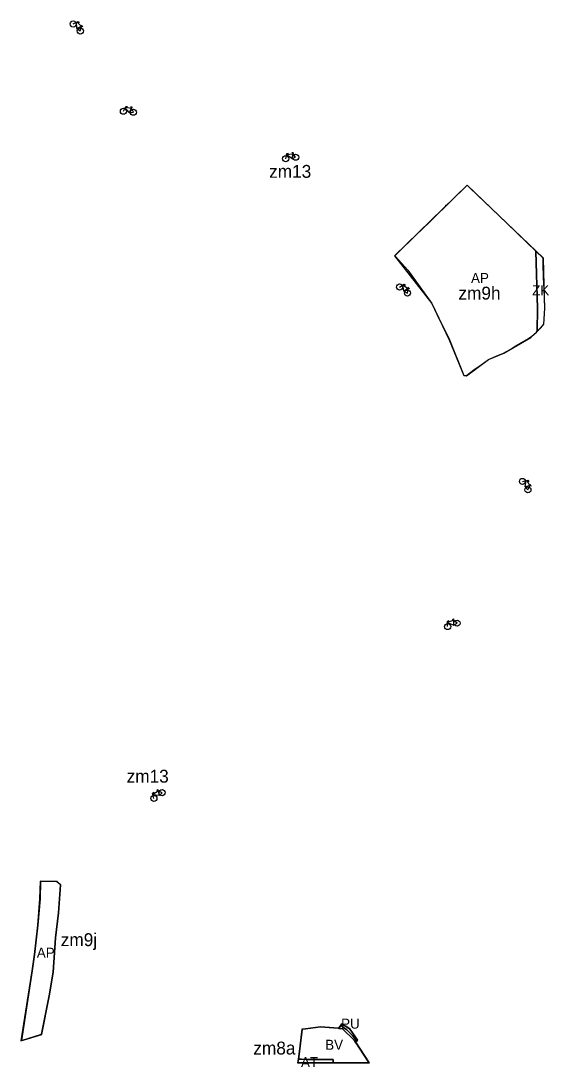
# Model space of a CAD drawing. Extents: x -555070 to -553076, y -1186731 to -1182766.
# Drawn here: x -554996 to -554258, y -1184227 to -1182766 of the extents above; entities that cross this region are included whole.
import ezdxf

# ---------------------------------------------------------------- set-up
doc = ezdxf.new("R2010")
doc.units = 0
for name, color, linetype in [('HRANICE_ZMENY_DO_KOO', 7, 'Continuous'), ('Level 10', 7, 'Continuous'), ('Level 13', 7, 'Continuous'), ('Level 52', 7, 'Continuous'), ('Level 58', 7, 'Continuous'), ('Level 59', 7, 'Continuous'), ('MISTNI_KOMUNIKACE_stav', 7, 'Continuous'), ('OBRYS_PLOCH', 7, 'Continuous'), ('stav_AP', 7, 'Continuous'), ('stav_AT', 7, 'Continuous'), ('stav_BV', 7, 'Continuous'), ('stav_PU', 7, 'Continuous'), ('stav_ZK', 7, 'Continuous'), ('ZU_plocha_aktualizace', 7, 'Continuous')]:
    doc.layers.add(name, color=color, linetype=linetype)

msp = doc.modelspace()

# ---------------------------------------------------------------- linework, layer by layer
at = {"layer": 'HRANICE_ZMENY_DO_KOO'}
for points in [[(-554368.6, -1182998.9), (-554372.7, -1182994.9), (-554473.9, -1183093.6), (-554421.9, -1183160.4), (-554397.6, -1183211.2), (-554377.3, -1183261), (-554373.3, -1183261.3), (-554342.6, -1183238.7), (-554321.4, -1183229.8), (-554283.7, -1183207.7), (-554274.5, -1183199.2), (-554265.2, -1183189.4), (-554263.8, -1183167.5), (-554265, -1183134), (-554266, -1183097)], [(-554940.1, -1183972.4), (-554945.6, -1183967.6), (-554969.2, -1183967.3), (-554969.9, -1183991.9), (-554973.1, -1184028.8), (-554977.7, -1184069.8), (-554980.9, -1184092.6), (-554996.1, -1184190.5), (-554966.8, -1184181.4), (-554956.2, -1184127.4), (-554950.7, -1184094.4), (-554947.3, -1184046.6), (-554943, -1184011.7)], [(-554528.1, -1184191.6), (-554525.1, -1184189.4), (-554529, -1184183.7), (-554532.4, -1184179), (-554535.8, -1184174.1), (-554542.2, -1184170), (-554547.9, -1184166.5), (-554552.1, -1184172.7), (-554577.5, -1184170.7), (-554598.4, -1184173.4), (-554603.4, -1184174.1), (-554607.9, -1184209), (-554608.8, -1184215.8), (-554609.5, -1184221.2), (-554559.9, -1184221.3), (-554535.4, -1184221.3), (-554526.4, -1184221.3), (-554519.6, -1184221.3), (-554509, -1184221.3)]]:
    msp.add_lwpolyline(points, close=True, dxfattribs=at)
at = {"layer": 'Level 13'}
for p, q in [((-554968.7, -1183967.9), (-554969.4, -1183991.9)), ((-554945.8, -1183968.1), (-554968.7, -1183967.9)), ((-554940.6, -1183972.6), (-554945.8, -1183968.1)), ((-554943.5, -1184011.7), (-554940.6, -1183972.6)), ((-554969.4, -1183991.9), (-554972.6, -1184028.9)), ((-554947.8, -1184046.5), (-554943.5, -1184011.7)), ((-554972.6, -1184028.9), (-554977.2, -1184069.9)), ((-554951.2, -1184094.3), (-554947.8, -1184046.5)), ((-554977.2, -1184069.9), (-554980.4, -1184092.7)), ((-554980.4, -1184092.7), (-554995.5, -1184189.8)), ((-554956.7, -1184127.3), (-554951.2, -1184094.3)), ((-554967.3, -1184181), (-554956.7, -1184127.3)), ((-554547.8, -1184167.2), (-554550.3, -1184170.9)), ((-554542.4, -1184170.4), (-554547.8, -1184167.2)), ((-554995.5, -1184189.8), (-554967.3, -1184181)), ((-554603, -1184174.5), (-554607.4, -1184209)), ((-554598.3, -1184173.9), (-554603, -1184174.5)), ((-554577.5, -1184171.2), (-554598.3, -1184173.9)), ((-554551.9, -1184173.2), (-554577.5, -1184171.2)), ((-554550.3, -1184170.9), (-554551.9, -1184173.2)), ((-554536.1, -1184174.5), (-554542.4, -1184170.4)), ((-554532.8, -1184179.3), (-554536.1, -1184174.5)), ((-554528.8, -1184191.5), (-554525.8, -1184189.3)), ((-554528.8, -1184191.5), (-554528.8, -1184191.5)), ((-554509.9, -1184220.8), (-554528.8, -1184191.5)), ((-554607.4, -1184209), (-554608.3, -1184215.8)), ((-554608.3, -1184215.8), (-554608.9, -1184220.7)), ((-554608.9, -1184220.7), (-554559.9, -1184220.8)), ((-554559.9, -1184220.8), (-554535.4, -1184220.8)), ((-554535.4, -1184220.8), (-554526.4, -1184220.8)), ((-554526.4, -1184220.8), (-554519.6, -1184220.8)), ((-554519.6, -1184220.8), (-554509.9, -1184220.8))]:
    msp.add_line(p, q, dxfattribs=at)
msp.add_lwpolyline([(-554525.8, -1184189.3), (-554529.4, -1184184), (-554532.8, -1184179.3)], dxfattribs=at)
at = {"layer": 'Level 52'}
msp.add_lwpolyline([(-554525.8, -1184189.3), (-554529.4, -1184184), (-554532.8, -1184179.3), (-554536.1, -1184174.5), (-554542.4, -1184170.4), (-554547.8, -1184167.2), (-554550.3, -1184170.9), (-554551.9, -1184173.2), (-554577.5, -1184171.2), (-554598.3, -1184173.9), (-554603, -1184174.5), (-554607.4, -1184209), (-554608.3, -1184215.8), (-554603.8, -1184216.1), (-554559.9, -1184216.7), (-554559.9, -1184220.8)], dxfattribs=at)
at = {"layer": 'Level 58'}
for p, q in [((-554923.1, -1182769.8), (-554916.2, -1182766.5)), ((-554917.8, -1182776.3), (-554918.2, -1182767.5)), ((-554910.3, -1182772.9), (-554917.8, -1182776.3)), ((-554917.8, -1182776.3), (-554913.1, -1182779.6)), ((-554917.5, -1182767.2), (-554911.6, -1182773.4)), ((-554916.2, -1182766.5), (-554914.5, -1182768.3)), ((-554913.1, -1182779.6), (-554911.6, -1182773.4)), ((-554910.3, -1182772.9), (-554911.6, -1182771.6)), ((-554910.3, -1182772.9), (-554909.6, -1182773.6)), ((-554852.8, -1182891.7), (-554849.5, -1182884.9)), ((-554844.6, -1182893.4), (-554850.5, -1182886.9)), ((-554850.1, -1182886.2), (-554841.6, -1182887.3)), ((-554849.5, -1182884.9), (-554847.1, -1182885.1)), ((-554840.9, -1182886.1), (-554844.6, -1182893.4)), ((-554844.6, -1182893.4), (-554838.9, -1182893.1)), ((-554840.9, -1182886.1), (-554842.8, -1182885.9)), ((-554838.9, -1182893.1), (-554841.6, -1182887.3)), ((-554840.9, -1182886.1), (-554840, -1182886.2)), ((-554626.1, -1182958), (-554624.5, -1182950.6)), ((-554617.7, -1182957.7), (-554624.9, -1182952.7)), ((-554624.8, -1182952), (-554616.2, -1182951.1)), ((-554624.5, -1182950.6), (-554622, -1182950.3)), ((-554615.9, -1182949.7), (-554617.7, -1182957.7)), ((-554615.9, -1182949.7), (-554617.7, -1182950)), ((-554612.2, -1182956), (-554616.2, -1182951.1)), ((-554615.9, -1182949.7), (-554614.9, -1182949.6)), ((-554617.7, -1182957.7), (-554612.2, -1182956)), ((-554467, -1183137.3), (-554460.5, -1183133.2)), ((-554460.9, -1183143.1), (-554462.4, -1183134.4)), ((-554461.8, -1183134), (-554455.1, -1183139.6)), ((-554453.9, -1183138.9), (-554460.9, -1183143.1)), ((-554460.9, -1183143.1), (-554455.9, -1183145.8)), ((-554460.5, -1183133.2), (-554458.6, -1183134.8)), ((-554455.9, -1183145.8), (-554455.1, -1183139.6)), ((-554453.9, -1183138.9), (-554455.3, -1183137.7)), ((-554453.9, -1183138.9), (-554453.2, -1183139.5)), ((-554295.2, -1183408.9), (-554287.8, -1183407.2)), ((-554291.4, -1183416.4), (-554289.9, -1183407.7)), ((-554289.2, -1183407.5), (-554284.8, -1183414.9)), ((-554287.8, -1183407.2), (-554286.5, -1183409.3)), ((-554283.4, -1183414.6), (-554291.4, -1183416.4)), ((-554291.4, -1183416.4), (-554287.6, -1183420.6)), ((-554287.6, -1183420.6), (-554284.8, -1183414.9)), ((-554283.4, -1183414.6), (-554284.4, -1183413.1)), ((-554283.4, -1183414.6), (-554282.9, -1183415.5)), ((-554399.8, -1183605.6), (-554391.6, -1183602.9)), ((-554399.8, -1183604.1), (-554397.5, -1183603.3)), ((-554399.8, -1183611.7), (-554399.8, -1183604.1)), ((-554391.7, -1183609.7), (-554399.8, -1183606.3)), ((-554391.6, -1183601.5), (-554393.3, -1183602.1)), ((-554391.6, -1183601.5), (-554391.7, -1183609.7)), ((-554391.7, -1183609.7), (-554386.7, -1183606.9)), ((-554391.6, -1183601.5), (-554390.6, -1183601.2)), ((-554386.7, -1183606.9), (-554391.6, -1183602.9)), ((-554812.2, -1183844.3), (-554810.1, -1183843)), ((-554810.3, -1183851.7), (-554812.2, -1183844.3)), ((-554811.8, -1183845.8), (-554804.5, -1183841.1)), ((-554802.9, -1183847.7), (-554811.6, -1183846.5)), ((-554804.9, -1183839.7), (-554806.4, -1183840.8)), ((-554804.9, -1183839.7), (-554804, -1183839.2)), ((-554804.9, -1183839.7), (-554802.9, -1183847.7)), ((-554798.8, -1183843.7), (-554804.5, -1183841.1)), ((-554802.9, -1183847.7), (-554798.8, -1183843.7))]:
    msp.add_line(p, q, dxfattribs=at)
for centre in [(-554923.1, -1182769.8), (-554913.1, -1182779.6), (-554852.8, -1182891.7), (-554838.9, -1182893.1), (-554626.1, -1182958), (-554612.2, -1182956), (-554467, -1183137.3), (-554455.9, -1183145.8), (-554295.2, -1183408.9), (-554287.6, -1183420.6), (-554399.8, -1183611.7), (-554386.7, -1183606.9), (-554798.8, -1183843.7), (-554810.3, -1183851.7)]:
    msp.add_circle(centre, 4.25, dxfattribs=at)
at = {"layer": 'MISTNI_KOMUNIKACE_stav'}
msp.add_lwpolyline([(-554527.1, -1184190.4), (-554532.9, -1184183), (-554540.7, -1184174.9), (-554545.4, -1184171.7), (-554549.3, -1184168.9)], dxfattribs=at)
at = {"layer": 'OBRYS_PLOCH'}
for p, q in [((-554372.7, -1182995.2), (-554378.1, -1183000.5)), ((-554316.8, -1183048.7), (-554372.7, -1182995.2)), ((-554390.4, -1183012.4), (-554394.3, -1183016.3)), ((-554386.4, -1183008.6), (-554390.4, -1183012.4)), ((-554382.3, -1183004.6), (-554386.4, -1183008.6)), ((-554378.1, -1183000.5), (-554382.3, -1183004.6)), ((-554403.3, -1183025.1), (-554414, -1183035.5)), ((-554402.7, -1183023.1), (-554403.3, -1183025.1)), ((-554402, -1183023.8), (-554402.7, -1183023.1)), ((-554398.2, -1183020.1), (-554402, -1183023.8)), ((-554394.3, -1183016.3), (-554398.2, -1183020.1)), ((-554414, -1183035.5), (-554424.8, -1183046)), ((-554435.6, -1183056.5), (-554444.2, -1183065)), ((-554424.8, -1183046), (-554435.6, -1183056.5)), ((-554276.5, -1183087.3), (-554316.8, -1183048.7)), ((-554444.2, -1183065), (-554454.1, -1183074.7)), ((-554464.8, -1183085), (-554469.5, -1183089.6)), ((-554460, -1183080.4), (-554464.8, -1183085)), ((-554454.1, -1183074.7), (-554460, -1183080.4)), ((-554266.2, -1183097.1), (-554276.5, -1183087.3)), ((-554276.5, -1183087.3), (-554274, -1183167.3)), ((-554274, -1183167.3), (-554276.5, -1183087.3)), ((-554469.5, -1183089.6), (-554473.6, -1183093.6)), ((-554473.6, -1183093.6), (-554472.1, -1183094.9)), ((-554472.1, -1183094.9), (-554455.4, -1183113.9)), ((-554266.2, -1183107.8), (-554266.2, -1183097.1)), ((-554455.4, -1183113.9), (-554421.7, -1183160.3)), ((-554265.8, -1183121.5), (-554266.2, -1183107.8)), ((-554265.2, -1183134), (-554265.8, -1183121.5)), ((-554264.9, -1183138.9), (-554265.2, -1183134)), ((-554421.7, -1183160.3), (-554414.7, -1183175.1)), ((-554274, -1183167.3), (-554274.6, -1183199.1)), ((-554274.6, -1183199.1), (-554274, -1183167.3)), ((-554414.7, -1183175.1), (-554397.3, -1183211.1)), ((-554269.6, -1183194.3), (-554265.4, -1183189.3)), ((-554282.4, -1183206.3), (-554275.8, -1183200.2)), ((-554275.8, -1183200.2), (-554274.6, -1183199.1)), ((-554274.6, -1183199.1), (-554269.6, -1183194.3)), ((-554397.3, -1183211.1), (-554377.1, -1183260.8)), ((-554304.4, -1183219.6), (-554296.6, -1183214.9)), ((-554296.6, -1183214.9), (-554289.3, -1183210.5)), ((-554289.3, -1183210.5), (-554282.4, -1183206.3)), ((-554332, -1183234), (-554321.5, -1183229.7)), ((-554321.5, -1183229.7), (-554312.4, -1183224.5)), ((-554312.4, -1183224.5), (-554304.4, -1183219.6)), ((-554363.2, -1183253.1), (-554353, -1183245.9)), ((-554353, -1183245.9), (-554342.7, -1183238.5)), ((-554342.7, -1183238.5), (-554332, -1183234)), ((-554377.1, -1183260.8), (-554373.4, -1183261.1)), ((-554373.4, -1183261.1), (-554363.2, -1183253.1)), ((-554968.7, -1183967.9), (-554969.4, -1183991.9)), ((-554945.8, -1183968.1), (-554968.7, -1183967.9)), ((-554940.6, -1183972.6), (-554945.8, -1183968.1)), ((-554943.5, -1184011.7), (-554940.6, -1183972.6)), ((-554969.4, -1183991.9), (-554972.6, -1184028.9)), ((-554947.8, -1184046.5), (-554943.5, -1184011.7)), ((-554972.6, -1184028.9), (-554977.2, -1184069.9)), ((-554951.2, -1184094.3), (-554947.8, -1184046.5)), ((-554977.2, -1184069.9), (-554980.4, -1184092.7)), ((-554980.4, -1184092.7), (-554995.5, -1184189.8)), ((-554956.7, -1184127.3), (-554951.2, -1184094.3)), ((-554967.3, -1184181), (-554956.7, -1184127.3)), ((-554547.8, -1184167.2), (-554550.3, -1184170.9)), ((-554542.4, -1184170.4), (-554547.8, -1184167.2)), ((-554995.5, -1184189.8), (-554967.3, -1184181)), ((-554603, -1184174.5), (-554607.4, -1184209)), ((-554603, -1184174.5), (-554607.4, -1184209)), ((-554598.3, -1184173.9), (-554603, -1184174.5)), ((-554598.3, -1184173.9), (-554603, -1184174.5)), ((-554577.5, -1184171.2), (-554598.3, -1184173.9)), ((-554577.5, -1184171.2), (-554598.3, -1184173.9)), ((-554546.6, -1184173.6), (-554577.5, -1184171.2)), ((-554551.9, -1184173.2), (-554577.5, -1184171.2)), ((-554550.3, -1184170.9), (-554551.9, -1184173.2)), ((-554551.9, -1184173.2), (-554546.6, -1184173.6)), ((-554546.6, -1184173.6), (-554551.9, -1184173.2)), ((-554530.2, -1184189.3), (-554546.6, -1184173.6)), ((-554546.6, -1184173.6), (-554530.2, -1184189.3)), ((-554530.2, -1184189.3), (-554546.6, -1184173.6)), ((-554536.1, -1184174.5), (-554542.4, -1184170.4)), ((-554532.8, -1184179.3), (-554536.1, -1184174.5)), ((-554528.8, -1184191.5), (-554530.2, -1184189.3)), ((-554530.2, -1184189.3), (-554528.8, -1184191.5)), ((-554528.8, -1184191.5), (-554530.2, -1184189.3)), ((-554528.8, -1184191.5), (-554525.8, -1184189.3)), ((-554509.9, -1184220.8), (-554528.8, -1184191.5)), ((-554509.9, -1184220.8), (-554528.8, -1184191.5)), ((-554607.4, -1184209), (-554608.3, -1184215.8)), ((-554607.4, -1184209), (-554608.3, -1184215.8)), ((-554608.3, -1184215.8), (-554608.9, -1184220.7)), ((-554608.3, -1184215.8), (-554608.9, -1184220.7)), ((-554608.9, -1184220.7), (-554559.9, -1184220.8)), ((-554608.9, -1184220.7), (-554559.9, -1184220.8)), ((-554603.8, -1184216.1), (-554608.3, -1184215.8)), ((-554608.3, -1184215.8), (-554603.8, -1184216.1)), ((-554597.6, -1184216.5), (-554603.8, -1184216.1)), ((-554603.8, -1184216.1), (-554597.6, -1184216.5)), ((-554570.2, -1184216.6), (-554597.6, -1184216.5)), ((-554597.6, -1184216.5), (-554570.2, -1184216.6)), ((-554559.9, -1184216.7), (-554570.2, -1184216.6)), ((-554570.2, -1184216.6), (-554559.9, -1184216.7)), ((-554559.9, -1184220.8), (-554559.9, -1184216.7)), ((-554559.9, -1184216.7), (-554559.9, -1184220.8)), ((-554559.9, -1184220.8), (-554535.4, -1184220.8)), ((-554559.9, -1184220.8), (-554535.4, -1184220.8)), ((-554535.4, -1184220.8), (-554526.4, -1184220.8)), ((-554535.4, -1184220.8), (-554526.4, -1184220.8)), ((-554526.4, -1184220.8), (-554519.6, -1184220.8)), ((-554526.4, -1184220.8), (-554519.6, -1184220.8)), ((-554519.6, -1184220.8), (-554509.9, -1184220.8)), ((-554519.6, -1184220.8), (-554509.9, -1184220.8))]:
    msp.add_line(p, q, dxfattribs=at)
for points in [[(-554265.4, -1183189.3), (-554264, -1183167.5), (-554264.9, -1183138.9)], [(-554525.8, -1184189.3), (-554529.4, -1184184), (-554532.8, -1184179.3)]]:
    msp.add_lwpolyline(points, dxfattribs=at)
at = {"layer": 'stav_AP'}
for p, q in [((-554372.7, -1182995.2), (-554378.1, -1183000.5)), ((-554316.8, -1183048.7), (-554372.7, -1182995.2)), ((-554390.4, -1183012.4), (-554394.3, -1183016.3)), ((-554386.4, -1183008.6), (-554390.4, -1183012.4)), ((-554382.3, -1183004.6), (-554386.4, -1183008.6)), ((-554378.1, -1183000.5), (-554382.3, -1183004.6)), ((-554403.3, -1183025.1), (-554414, -1183035.5)), ((-554402.7, -1183023.1), (-554403.3, -1183025.1)), ((-554402, -1183023.8), (-554402.7, -1183023.1)), ((-554398.2, -1183020.1), (-554402, -1183023.8)), ((-554394.3, -1183016.3), (-554398.2, -1183020.1)), ((-554414, -1183035.5), (-554424.8, -1183046)), ((-554435.6, -1183056.5), (-554444.2, -1183065)), ((-554424.8, -1183046), (-554435.6, -1183056.5)), ((-554276.5, -1183087.3), (-554316.8, -1183048.7)), ((-554444.2, -1183065), (-554454.1, -1183074.7)), ((-554464.8, -1183085), (-554469.5, -1183089.6)), ((-554460, -1183080.4), (-554464.8, -1183085)), ((-554454.1, -1183074.7), (-554460, -1183080.4)), ((-554274, -1183167.3), (-554276.5, -1183087.3)), ((-554469.5, -1183089.6), (-554473.6, -1183093.6)), ((-554473.6, -1183093.6), (-554472.1, -1183094.9)), ((-554472.1, -1183094.9), (-554455.4, -1183113.9)), ((-554455.4, -1183113.9), (-554421.7, -1183160.3)), ((-554421.7, -1183160.3), (-554414.7, -1183175.1)), ((-554274.6, -1183199.1), (-554274, -1183167.3)), ((-554414.7, -1183175.1), (-554397.3, -1183211.1)), ((-554282.4, -1183206.3), (-554275.8, -1183200.2)), ((-554275.8, -1183200.2), (-554274.6, -1183199.1)), ((-554397.3, -1183211.1), (-554377.1, -1183260.8)), ((-554304.4, -1183219.6), (-554296.6, -1183214.9)), ((-554296.6, -1183214.9), (-554289.3, -1183210.5)), ((-554289.3, -1183210.5), (-554282.4, -1183206.3)), ((-554332, -1183234), (-554321.5, -1183229.7)), ((-554321.5, -1183229.7), (-554312.4, -1183224.5)), ((-554312.4, -1183224.5), (-554304.4, -1183219.6)), ((-554363.2, -1183253.1), (-554353, -1183245.9)), ((-554353, -1183245.9), (-554342.7, -1183238.5)), ((-554342.7, -1183238.5), (-554332, -1183234)), ((-554377.1, -1183260.8), (-554373.4, -1183261.1)), ((-554373.4, -1183261.1), (-554363.2, -1183253.1)), ((-554968.7, -1183967.9), (-554969.4, -1183991.9)), ((-554945.8, -1183968.1), (-554968.7, -1183967.9)), ((-554940.6, -1183972.6), (-554945.8, -1183968.1)), ((-554943.5, -1184011.7), (-554940.6, -1183972.6)), ((-554969.4, -1183991.9), (-554972.6, -1184028.9)), ((-554947.8, -1184046.5), (-554943.5, -1184011.7)), ((-554972.6, -1184028.9), (-554977.2, -1184069.9)), ((-554951.2, -1184094.3), (-554947.8, -1184046.5)), ((-554977.2, -1184069.9), (-554980.4, -1184092.7)), ((-554980.4, -1184092.7), (-554995.5, -1184189.8)), ((-554956.7, -1184127.3), (-554951.2, -1184094.3)), ((-554967.3, -1184181), (-554956.7, -1184127.3)), ((-554995.5, -1184189.8), (-554967.3, -1184181))]:
    msp.add_line(p, q, dxfattribs=at)
at = {"layer": 'stav_AT'}
for p, q in [((-554608.3, -1184215.8), (-554608.9, -1184220.7)), ((-554608.9, -1184220.7), (-554559.9, -1184220.8)), ((-554603.8, -1184216.1), (-554608.3, -1184215.8)), ((-554597.6, -1184216.5), (-554603.8, -1184216.1)), ((-554570.2, -1184216.6), (-554597.6, -1184216.5)), ((-554559.9, -1184216.7), (-554570.2, -1184216.6)), ((-554559.9, -1184220.8), (-554559.9, -1184216.7))]:
    msp.add_line(p, q, dxfattribs=at)
at = {"layer": 'stav_BV'}
for p, q in [((-554603, -1184174.5), (-554607.4, -1184209)), ((-554598.3, -1184173.9), (-554603, -1184174.5)), ((-554577.5, -1184171.2), (-554598.3, -1184173.9)), ((-554530.2, -1184189.3), (-554546.6, -1184173.6)), ((-554528.8, -1184191.5), (-554530.2, -1184189.3)), ((-554509.9, -1184220.8), (-554528.8, -1184191.5)), ((-554607.4, -1184209), (-554608.3, -1184215.8)), ((-554608.3, -1184215.8), (-554603.8, -1184216.1)), ((-554603.8, -1184216.1), (-554597.6, -1184216.5)), ((-554597.6, -1184216.5), (-554570.2, -1184216.6)), ((-554570.2, -1184216.6), (-554559.9, -1184216.7)), ((-554559.9, -1184216.7), (-554559.9, -1184220.8)), ((-554559.9, -1184220.8), (-554535.4, -1184220.8)), ((-554535.4, -1184220.8), (-554526.4, -1184220.8)), ((-554526.4, -1184220.8), (-554519.6, -1184220.8)), ((-554519.6, -1184220.8), (-554509.9, -1184220.8))]:
    msp.add_line(p, q, dxfattribs=at)
msp.add_lwpolyline([(-554546.6, -1184173.6), (-554551.9, -1184173.2), (-554577.5, -1184171.2)], dxfattribs=at)
at = {"layer": 'stav_PU'}
for p, q in [((-554547.8, -1184167.2), (-554550.3, -1184170.9)), ((-554542.4, -1184170.4), (-554547.8, -1184167.2)), ((-554550.3, -1184170.9), (-554551.9, -1184173.2)), ((-554551.9, -1184173.2), (-554546.6, -1184173.6)), ((-554546.6, -1184173.6), (-554530.2, -1184189.3)), ((-554536.1, -1184174.5), (-554542.4, -1184170.4)), ((-554532.8, -1184179.3), (-554536.1, -1184174.5)), ((-554530.2, -1184189.3), (-554528.8, -1184191.5)), ((-554528.8, -1184191.5), (-554525.8, -1184189.3))]:
    msp.add_line(p, q, dxfattribs=at)
msp.add_lwpolyline([(-554525.8, -1184189.3), (-554529.4, -1184184), (-554532.8, -1184179.3)], dxfattribs=at)
at = {"layer": 'stav_ZK'}
for p, q in [((-554266.2, -1183097.1), (-554276.5, -1183087.3)), ((-554276.5, -1183087.3), (-554274, -1183167.3)), ((-554266.2, -1183107.8), (-554266.2, -1183097.1)), ((-554265.8, -1183121.5), (-554266.2, -1183107.8)), ((-554265.2, -1183134), (-554265.8, -1183121.5)), ((-554264.9, -1183138.9), (-554265.2, -1183134)), ((-554274, -1183167.3), (-554274.6, -1183199.1)), ((-554269.6, -1183194.3), (-554265.4, -1183189.3)), ((-554274.6, -1183199.1), (-554269.6, -1183194.3))]:
    msp.add_line(p, q, dxfattribs=at)
msp.add_lwpolyline([(-554265.4, -1183189.3), (-554264, -1183167.5), (-554264.9, -1183138.9)], dxfattribs=at)
at = {"layer": 'ZU_plocha_aktualizace'}
for p, q in [((-554547.8, -1184167.2), (-554549.1, -1184169.1)), ((-554542.4, -1184170.4), (-554547.8, -1184167.2)), ((-554603, -1184174.5), (-554607.4, -1184209)), ((-554598.3, -1184173.9), (-554603, -1184174.5)), ((-554577.5, -1184171.2), (-554598.3, -1184173.9)), ((-554550.3, -1184170.9), (-554551.9, -1184173.2)), ((-554551.9, -1184173.2), (-554546.6, -1184173.6)), ((-554549.1, -1184169.1), (-554550.3, -1184170.9)), ((-554549.1, -1184169.1), (-554545.4, -1184171.7)), ((-554545.4, -1184171.7), (-554549.1, -1184169.1)), ((-554530.2, -1184189.3), (-554546.6, -1184173.6)), ((-554546.6, -1184173.6), (-554530.2, -1184189.3)), ((-554536.1, -1184174.5), (-554542.4, -1184170.4)), ((-554527.2, -1184190.3), (-554532.9, -1184183)), ((-554528.8, -1184191.5), (-554530.2, -1184189.3)), ((-554530.2, -1184189.3), (-554528.8, -1184191.5)), ((-554529, -1184191.9), (-554528.7, -1184191.7)), ((-554525.5, -1184196.7), (-554529, -1184191.9)), ((-554528.8, -1184191.5), (-554527.2, -1184190.3)), ((-554528.7, -1184191.7), (-554528.8, -1184191.5)), ((-554527.2, -1184190.3), (-554525.8, -1184189.3)), ((-554509.9, -1184220.8), (-554525.5, -1184196.7)), ((-554607.4, -1184209), (-554608.3, -1184215.8)), ((-554559.9, -1184220.8), (-554535.4, -1184220.8)), ((-554535.4, -1184220.8), (-554526.4, -1184220.8)), ((-554526.4, -1184220.8), (-554519.6, -1184220.8)), ((-554519.6, -1184220.8), (-554509.9, -1184220.8))]:
    msp.add_line(p, q, dxfattribs=at)
for points in [[(-554546.6, -1184173.6), (-554551.9, -1184173.2), (-554577.5, -1184171.2)], [(-554545.4, -1184171.7), (-554540.7, -1184174.9), (-554532.9, -1184183), (-554527.2, -1184190.3)], [(-554532.9, -1184183), (-554540.7, -1184174.9), (-554545.4, -1184171.7)], [(-554525.8, -1184189.3), (-554529.4, -1184184), (-554532.8, -1184179.3), (-554536.1, -1184174.5)], [(-554608.3, -1184215.8), (-554603.8, -1184216.1), (-554559.9, -1184216.7), (-554559.9, -1184220.8)]]:
    msp.add_lwpolyline(points, dxfattribs=at)

# ---------------------------------------------------------------- texts
at = {"layer": 'Level 10'}
for s, p in [('zm13', (-554649.2, -1182984.7)), ('zm9h', (-554384.7, -1183154.8)), ('zm13', (-554848.4, -1183829.7)), ('zm9j', (-554940.4, -1184058.1)), ('zm8a', (-554671.3, -1184209.5))]:
    msp.add_text(s, height=18, dxfattribs=at).set_placement(p)
at = {"layer": 'Level 59'}
for s, p in [('AP', (-554367.1, -1183131.7)), ('ZK', (-554281.7, -1183148.9)), ('AP', (-554973.9, -1184074.3)), ('PU', (-554548.6, -1184173.4)), ('BV', (-554570.9, -1184202.9)), ('AT', (-554604.7, -1184227.1))]:
    msp.add_text(s, height=14, dxfattribs=at).set_placement(p)

doc.saveas('drawing.dxf')
